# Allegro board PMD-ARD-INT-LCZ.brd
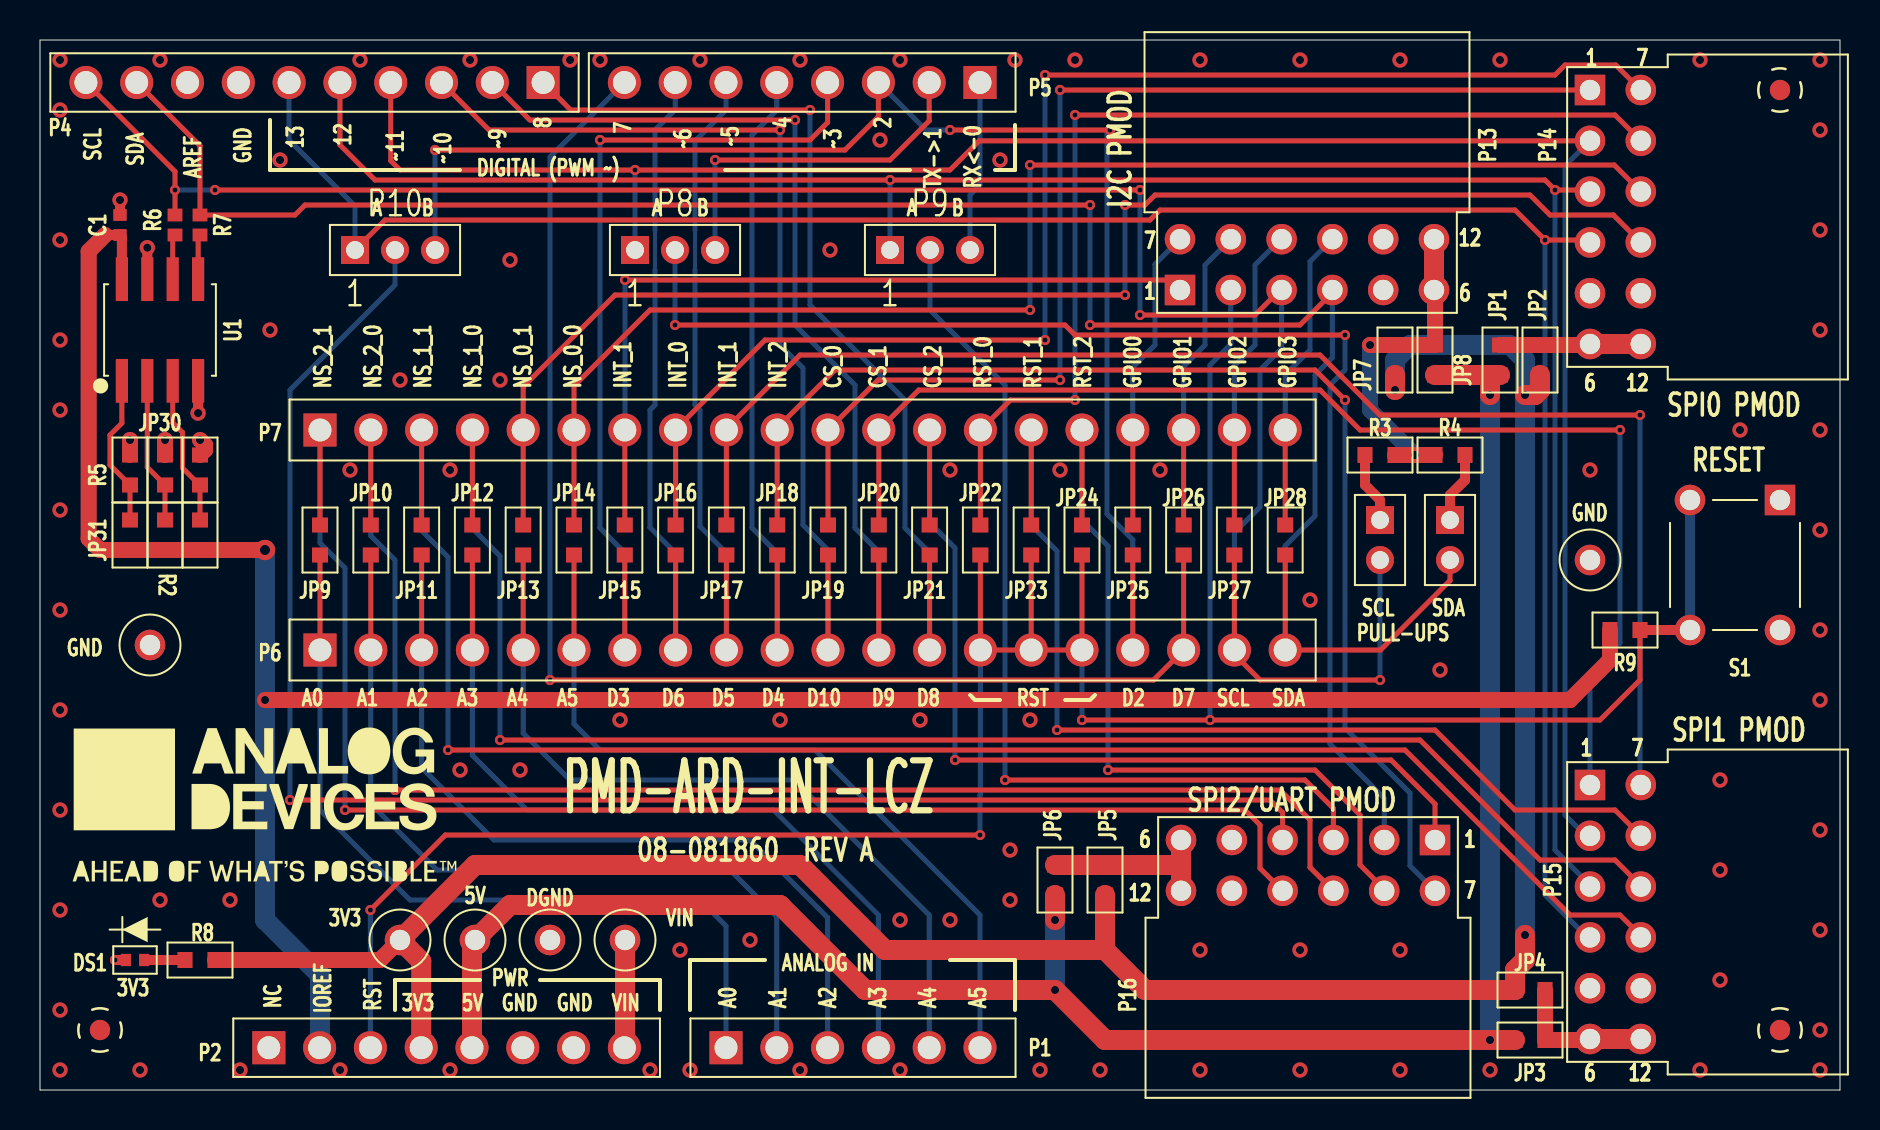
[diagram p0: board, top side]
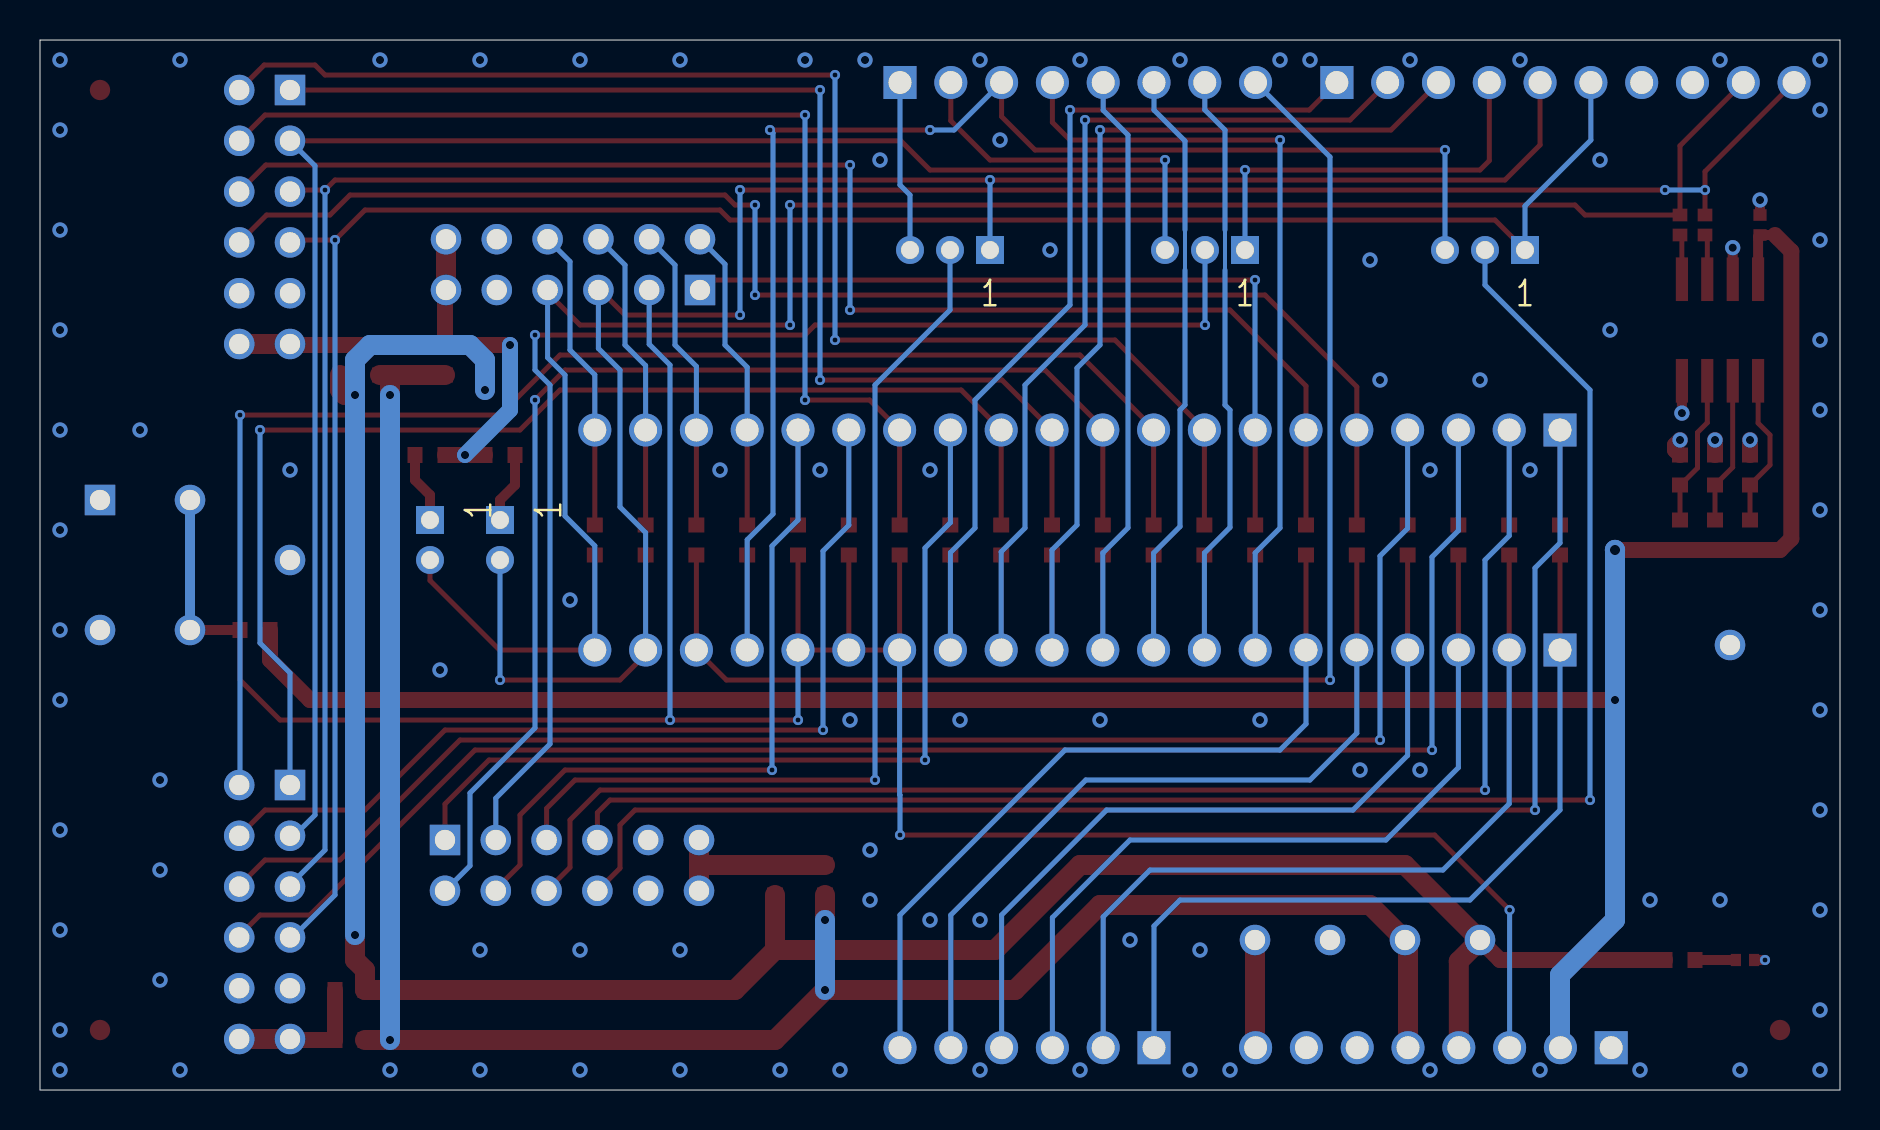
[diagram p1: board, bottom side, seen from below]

Outline 90 x 52.5 mm; copper layers: TOP, LAYER2, LAYER3, BOTTOM. Coordinates in mm from the lower left corner of the outline.
Outline path: 0,52.5 90,52.5 90,0 0,0 0,52.5

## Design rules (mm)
constraint set DEFAULT: min track width 0.15

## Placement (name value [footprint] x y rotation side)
C1  0.1uF  [C0402]  4 43.25 270 top
DGND  BLK  [CNKEY5001TP]  25.5 7.5 0 top
DGND1  BLK  [CNKEY5001TP]  5.5 22.25 0 top
DGND2  BLK  [CNKEY5001TP]  77.5 26.5 0 top
DS1  SML-P11MTT86R  [LED0402]  4.75 6.5 0 top
JP1  0  [R0603]  73 36.5 90 top
JP2  0  [R0603]  75 36.5 90 top
JP3  0  [R0603]  74.5 2.5 0 top
JP4  0  [R0603]  74.5 5 0 top
JP5  0  [R0603]  53.25 10.5 90 top
JP6  0  [R0603]  50.75 10.5 90 top
JP7  0  [R0603]  67.75 36.5 90 top
JP8  0  [R0603]  69.75 36.5 90 top
JP9  0  [R0603]  14 27.5 90 top
JP10  0  [R0603]  16.54 27.5 90 top
JP11  0  [R0603]  19.08 27.5 90 top
JP12  0  [R0603]  21.62 27.5 90 top
JP13  0  [R0603]  24.16 27.5 90 top
JP14  0  [R0603]  26.7 27.5 90 top
JP15  0  [R0603]  29.24 27.5 90 top
JP16  0  [R0603]  31.78 27.5 90 top
JP17  0  [R0603]  34.32 27.5 90 top
JP18  0  [R0603]  36.86 27.5 90 top
JP19  0  [R0603]  39.4 27.5 90 top
JP20  0  [R0603]  41.94 27.5 90 top
JP21  0  [R0603]  44.48 27.5 90 top
JP22  0  [R0603]  47.02 27.5 90 top
JP23  0  [R0603]  49.56 27.5 90 top
JP24  0  [R0603]  52.1 27.5 90 top
JP25  0  [R0603]  54.64 27.5 90 top
JP26  0  [R0603]  57.18 27.5 90 top
JP27  0  [R0603]  59.72 27.5 90 top
JP28  0  [R0603]  62.26 27.5 90 top
JP29  0  [R0603]  8 27.75 270 top
JP30  0  [R0603]  6.25 31 270 top
JP31  0  [R0603]  4.5 27.75 270 top
NOREF  -  []  -67.5 -75.55 0 top
NOREF#2  -  []  366.75 248.75 0 top
NOREF#3  -  []  0 53 270 top
NOREF#4  -  [unnamed#2]  3 3 180 top
NOREF#5  -  []  -43.25 -76.25 0 top
NOREF#6  -  []  11.25 14.25 0 top
NOREF#7  -  []  -43.25 -76.25 0 top
NOREF#8  -  []  0 0 90 top
NOREF#9  -  [unnamed#2]  87 3 180 top
NOREF#10  -  []  0 0 0 top
NOREF#11  -  []  90 0 90 top
NOREF#12  -  [unnamed#2]  87 50 90 top
NOREF#13  -  []  90 52.5 180 top
NOREF#14  -  []  231.75 23.75 0 top
NOREF#15  -  []  45.75 -10.25 0 top
NOREF#16  -  []  0 52.5 0 top
NOREF#17  -  []  -33.25 323.75 0 top
P1  SSQ-106-03-T-S  [CNSAMTECSSQ-106-XX-X-S]  34.3 2.12 0 top
P2  SSQ-108-03-T-S  [CNSAMTECSSQ-108-XX-X-S]  11.44 2.12 0 top
P4  SSQ-110-03-T-S  [CNSAMTECSSQ-110-XX-X-S]  25.16 50.38 180 top
P5  SSQ-108-03-T-S  [CNSAMTECSSQ-108-XX-X-S]  47 50.38 180 top
P6  TSW-120-17-T-S  [CNTHMHDR1X20L2000W100H733]  14 22 0 top
P7  TSW-120-17-T-S  [CNTHMHDR1X20L2000W100H733]  14 33 0 top
P8  62000311121  [CNTHMHDR1X3L236W79H244]  29.75 42 0 top
P9  62000311121  [CNTHMHDR1X3L236W79H244]  42.5 42 0 top
P10  62000311121  [CNTHMHDR1X3L236W79H244]  15.75 42 0 top
P11  62000211121  [CNTHMHDR1X2L157W79H250]  67 28.5 270 top
P12  62000211121  [CNTHMHDR1X2L157W79H250]  70.5 28.5 270 top
P13  PPPC062LJBN-RC  [CNHDRRA2X6H205]  57 40 0 top
P14  PPPC062LJBN-RC  [CNHDRRA2X6H205]  77.5 50 270 top
P15  Ø  [CNHDRRA2X6H205]  77.5 15.25 270 top
P16  PPPC062LJBN-RC  [CNHDRRA2X6H205]  69.75 12.5 180 top
R1  4.7K  [R0603]  8 31 270 top
R2  4.7K  [R0603]  6.25 27.75 270 top
R3  4.7K  [R0603]  67 31.75 0 top
R4  4.7K  [R0603]  70.5 31.75 180 top
R5  4.7K  [R0603]  4.5 31 270 top
R6  0  [R0402]  6.75 43.25 90 top
R7  0  [R0402]  8 43.25 90 top
R8  1K  [R0603]  8 6.5 0 top
R9  1K  [R0603]  79.25 23 180 top
S1  1825910-6  [SWTHSQ236H209]  87 29.5 180 top
U1  24AA32A-I/SN  [SO8]  6 38 0 top
UNK3V3  BLK  [CNKEY5001TP]  18 7.5 0 top
UNK5V  BLK  [CNKEY5001TP]  21.75 7.5 0 top
VIN  BLK  [CNKEY5001TP]  29.25 7.5 0 top

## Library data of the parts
C1 = CAP: User Part Number: UPN; Tolerance: 10; alternate symbols: (C0402); part number: CAP_SM-0.1UF,50V,10,E025746,C0402; tolerance: 10
DGND DGND1 DGND2 UNK3V3 UNK5V VIN = CNTP1P: Tolerance: N/A; User Part Number: UPN; alternate symbols: (CNKEY5001TP); part number: CNTP1P_TH-BLK,E022951,CNKEY5001TP; tolerance: N/A
DS1 = DIOLED: User Part Number: UPN; Tolerance: N/A; alternate symbols: (LED0402); part number: DIOLED_SM-SML-P11MTT86R,N/A,N/A,E014445,LED0402; tolerance: N/A
JP1-JP31 = RESJMPRSHRT: User Part Number: UPN; Tolerance: JUMPER; alternate symbols: (R0603); part number: RESJMPRSHRT_SM-0,E004447,1/10W,JUMPER,R0603; tolerance: JUMPER
P1 = CN6P: User Part Number: UPN; Tolerance: N/A; alternate symbols: (CNSAMTECSSQ-106-XX-X-S); part number: CN6P_TH-SSQ-106-03-T-S,E027150,CNSAMTECSSQ-106-XX-X-S; tolerance: N/A
P2 P5 = CN8P_A: User Part Number: UPN; Tolerance: N/A; alternate symbols: (CNSAMTECSSQ-108-XX-X-S); part number: CN8P_A_TH-SSQ-108-03-T-S,E027149,CNSAMTECSSQ-108-XX-X-S; tolerance: N/A
P4 = CN10P: User Part Number: UPN; Tolerance: N/A; alternate symbols: (CNSAMTECSSQ-110-XX-X-S); part number: CN10P_TH-SSQ-110-03-T-S,E027151,CNSAMTECSSQ-110-XX-X-S; tolerance: N/A
P6 P7 = CN20P: User Part Number: UPN; Tolerance: N/A; alternate symbols: (CNTHMHDR1X20L2000W100H733); part number: CN20P_TH-TSW-120-17-T-S,E055627,CNTHMHDR1X20L2000W100H733; tolerance: N/A
P8-P10 = CN3P: User Part Number: UPN; Tolerance: N/A; alternate symbols: (CNTHMHDR1X3L236W79H244); part number: CN3P_TH-62000311121,E033291,CNTHMHDR1X3L236W79H244; tolerance: N/A
P11 P12 = CN2P: User Part Number: UPN; Tolerance: N/A; alternate symbols: (CNTHMHDR1X2L157W79H250); part number: CN2P_TH-62000211121,E035205,CNTHMHDR1X2L157W79H250; tolerance: N/A
P13-P16 = CN12P_V3: User Part Number: UPN; Tolerance: N/A; alternate symbols: (CNHDRRA2X6H205); part number: CN12P_V3_TH-PPPC062LJBN-RC,E022332,CNHDRRA2X6H205; tolerance: N/A
R1-R5 = RES: User Part Number: UPN; Tolerance: 5; alternate symbols: (R0603); part number: RES_SM-4.7K,E031875,1/10W,5,R0603; tolerance: 5
R6 R7 = RES: User Part Number: UPN; Tolerance: JUMPER; alternate symbols: (R0402); part number: RES_SM-0,E003438,1/10W,JUMPER,R0402; tolerance: JUMPER
R8 R9 = RES: User Part Number: UPN; Tolerance: 1; alternate symbols: (R0603); part number: RES_SM-1K,E029591,1/10W,1,R0603; tolerance: 1
S1 = SWSPST4PIN_B: Tolerance: N/A; User Part Number: UPN; alternate symbols: (SWTHSQ236H209); part number: SWSPST4PIN_B_TH-1825910-6,E039562,SWTHSQ236H209; tolerance: N/A
U1 = IC24XX32A_V2: Tolerance: N/A; User Part Number: UPN; alternate symbols: (SO8); part number: IC24XX32A_V2_SM-24AA32A-I/SN,E034913,SO8; tolerance: N/A

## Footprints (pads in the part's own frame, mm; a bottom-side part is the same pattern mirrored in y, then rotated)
C0402
  rect 0.584x0.66 smd: 1(-0.5,0) 2(0.5,0)
CNHDRRA2X6H205
  rect 1.524x1.524 hole 1.016: 1(0,0)
  round 1.524 hole 1.016: 2(2.54,0) 3(5.08,0) 4(7.62,0) 5(10.16,0) 6(12.7,0) 7(0,2.54) 8(2.54,2.54) 9(5.08,2.54) 10(7.62,2.54) 11(10.16,2.54) 12(12.7,2.54)
CNKEY5001TP
  round 1.524 hole 1.016: 1(0,0)
CNSAMTECSSQ-106-XX-X-S
  rect 1.651x1.651 hole 1.143: 1(0,0)
  round 1.651 hole 1.143: 2(2.54,0) 3(5.08,0) 4(7.62,0) 5(10.16,0) 6(12.7,0)
CNSAMTECSSQ-108-XX-X-S
  rect 1.651x1.651 hole 1.143: 1(0,0)
  round 1.651 hole 1.143: 2(2.54,0) 3(5.08,0) 4(7.62,0) 5(10.16,0) 6(12.7,0) 7(15.24,0) 8(17.78,0)
CNSAMTECSSQ-110-XX-X-S
  rect 1.651x1.651 hole 1.143: 1(0,0)
  round 1.651 hole 1.143: 2(2.54,0) 3(5.08,0) 4(7.62,0) 5(10.16,0) 6(12.7,0) 7(15.24,0) 8(17.78,0) 9(20.32,0) 10(22.86,0)
CNTHMHDR1X2L157W79H250
  rect 1.397x1.397 hole 0.889: 1(0,0)
  round 1.397 hole 0.889: 2(2,0)
CNTHMHDR1X3L236W79H244
  rect 1.397x1.397 hole 0.889: 1(0,0)
  round 1.397 hole 0.889: 2(2,0) 3(4,0)
CNTHMHDR1X20L2000W100H733
  rect 1.651x1.651 hole 1.143: 1(0,0)
  round 1.651 hole 1.143: 2(2.54,0) 3(5.08,0) 4(7.62,0) 5(10.16,0) 6(12.7,0) 7(15.24,0) 8(17.78,0) 9(20.32,0) 10(22.86,0) 11(25.4,0) 12(27.94,0) 13(30.48,0) 14(33.02,0) 15(35.56,0) 16(38.1,0) 17(40.64,0) 18(43.18,0) 19(45.72,0) 20(48.26,0)
LED0402
  rect 0.508x0.61 smd: A(0.454,0) C(-0.454,0)
R0402
  rect 0.635x0.737 smd: 1(-0.5,0) 2(0.5,0)
R0603
  rect 0.75x0.8 smd: 1(-0.75,0) 2(0.75,0)
SO8
  rect 0.61x2.184 smd: 1(-1.905,-2.54) 2(-0.635,-2.54) 3(0.635,-2.54) 4(1.905,-2.54) 5(1.905,2.54) 6(0.635,2.54) 7(-0.635,2.54) 8(-1.905,2.54)
SWTHSQ236H209
  rect 1.524x1.524 hole 1.016: 1(0,0)
  round 1.524 hole 1.016: 2(0,6.5) 3(4.5,0) 4(4.5,6.5)
unnamed#2
  round 1.016 smd: (0,0)

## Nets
3V3_ARD: JP2.1 JP4.1 JP5.1 JP7.1 P2.4 R8.2(N2) UNK3V3.1
5V_ARD: JP1.1 JP3.1 JP6.1 JP8.1 P2.5 UNK5V.1
DGND: C1.1 DGND.1(N1) DGND1.1(N1) DGND2.1(N1) DS1.C JP30.1 P2.6 P2.7 P4.7 P13.5 P13.11 P14.5 P14.11 P15.5 P15.11 P16.5 P16.11 R1.1 R5.1 S1.1 S1.2 U1.4 U1.7(WP)
VIN: P2.8(N8) VIN.1(N1)
A0: JP9.1 P1.1 P6.1
A1: JP10.1 P1.2 P6.2
A2: JP11.1 P1.3 P6.3
A3: JP12.1 P1.4 P6.4
A4: JP13.1 P1.5 P6.5
A5: JP14.1 P1.6(N6) P6.6
CS_0: JP19.2(S2) P7.11 P14.1
CS_1: JP20.2(S2) P7.12 P15.1
CS_2: JP21.2(S2) P7.13 P16.1
D2: JP25.1 P5.3 P6.17 P10.3(N3)
D3: JP15.1 P5.4 P6.7
D4: JP18.1 P5.5 P6.10
D5: JP17.1 P5.6 P6.9(N9)
D6: JP16.1 P5.7 P6.8
D7: JP26.1 P5.8(N8) P6.18
D8: JP21.1 P4.1 P6.13
D9: JP20.1 P4.2 P6.12
D10: JP19.1 P4.3 P6.11
GPIO0: JP25.2(S2) P7.17 P13.7
GPIO1: JP26.2(S2) P7.18 P13.8
GPIO2: JP27.2(S2) P7.19 P13.9
GPIO3: JP28.2(S2) P7.20 P13.10
INT_0: JP16.2(S2) P7.8 P14.7
INT_1: JP17.2(S2) P7.9(N9) P15.7
INT_2: JP18.2(S2) P7.10 P16.7
INT_I: JP15.2(S2) P7.7 P13.1
IOREF_ARD: C1.2(N2) JP29.2(S2) JP31.2(S2) P2.2 R2.2(N2) R9.2(N2) U1.8
MISO_ARD: P4.5 P9.1 P14.3 P15.3
MOSI_ARD: P4.4 P8.1 P14.2 P15.2
NS_0_0: JP14.2(S2) P7.6 P14.9
NS_0_1: JP13.2(S2) P7.5 P14.10
NS_1_0: JP12.2(S2) P7.4 P15.9
NS_1_1: JP11.2(S2) P7.3 P15.10
NS_2_0: JP10.2(S2) P7.2 P16.9
NS_2_1: JP9.2(S2) P7.1 P16.10
RST_0: JP22.2(S2) P7.14 P14.8
RST_1: JP23.2(S2) P7.15 P15.8
RST_2: JP24.2(S2) P7.16 P16.8
RST_ARD: JP22.1 JP23.1 JP24.1 P2.3 P6.14 P6.15 P6.16 P13.2 R9.1 S1.3 S1.4(N4)
RX_ARD: P5.1 P9.3(N3)
SCK_ARD: P4.6 P10.1 P14.4 P15.4
SCL_ARD: JP27.1 P4.10 P6.19 P11.2(N2) P13.3 R6.2(N2)
SDA_ARD: JP28.1 P4.9(N9) P6.20 P12.2(N2) P13.4 R7.2(N2)
TX_ARD: P5.2 P8.3(N3)
UNNAMED_2_CN12PV3_I122_P2: P8.2 P16.2
UNNAMED_2_CN12PV3_I122_P3: P9.2 P16.3
UNNAMED_2_CN12PV3_I122_P4: P10.2 P16.4
UNNAMED_2_RES_I93_N1: P12.1 R4.1
UNNAMED_2_RES_I107_N1: P11.1 R3.1
UNNAMED_4_DIOLED_I89_P: DS1.A(P) R8.1
UNNAMED_4_IC24XX32AV2_I37_A0: JP31.1 R5.2(N2) U1.1
UNNAMED_4_IC24XX32AV2_I37_A1: JP30.2(S2) R2.1 U1.2
UNNAMED_4_IC24XX32AV2_I37_A2: JP29.1 R1.2(N2) U1.3
UNNAMED_4_IC24XX32AV2_I37_SCL: R6.1 U1.6
UNNAMED_4_IC24XX32AV2_I37_SDA: R7.1 U1.5
VPMOD_I2C: JP7.2(S2) JP8.2(S2) P13.6 P13.12(VCC2) R3.2(N2) R4.2(N2)
VPMOD_SPI0: JP1.2(S2) JP2.2(S2) P14.6 P14.12(VCC2)
VPMOD_SPI1: JP3.2(S2) JP4.2(S2) P15.6 P15.12(VCC2)
VPMOD_SPI2: JP5.2(S2) JP6.2(S2) P16.6 P16.12(VCC2)

Pads without a net: P2 1; P4 8

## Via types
v1: diameter 0.762, hole 0.406, TOP to BOTTOM, 107 vias
v2: diameter 0.508, hole 0.254, TOP to BOTTOM, 50 vias
v3: diameter 1.016, hole 0.508, TOP to BOTTOM, 1 via

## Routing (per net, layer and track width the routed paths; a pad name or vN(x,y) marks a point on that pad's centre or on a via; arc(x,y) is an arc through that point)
3V3_ARD: length 120.8
  TOP w0.8: R8.2 17,6.5 UNK3V3.1
  TOP w1: v1(74.25,34.75) 74.75,34.75 75,35 JP2.1 ; 53.25,7 42.25,7 38,11.25 21.75,11.25 UNK3V3.1 19.06,6.44 P2.4 ; 53.25,7 55.25,5 JP4.1 73.75,6 74.25,6.5 v1(74.25,7.75) ; 53.25,7 JP5.1 ; JP7.1 v1(67.75,35)
  BOTTOM w1: v1(67.75,35) 67.75,36.5 68.5,37.25 73.5,37.25 74.25,36.5 v1(74.25,34.75) v1(74.25,7.75)
5V_ARD: length 102.2
  TOP w1: JP6.1 v1(50.75,8.5) ; 72.55,35.75 JP1.1 ; 72.55,35.75 72.5,35.7 v1(72.5,34.75) ; 72.55,35.75 JP8.1 ; JP3.1 v1(72.5,2.5) 53.25,2.5 v1(50.75,5) 41.25,5 37,9.25 23.5,9.25 UNK5V.1 21.6,7.35 P2.5
  BOTTOM w1: v1(72.5,34.75) v1(72.5,2.5) ; v1(50.75,8.5) v1(50.75,5)
DGND: length 144.6
  TOP w0.5: C1.1 v1(4,44.5) ; U1.4 v1(7.91,33.84) ; U1.7 v1(5.37,42.12) ; DS1.C v2(3.75,6.5)
  TOP w0.8: v1(8,32.5) 8.25,32.25 8.25,32 R1.1 ; JP30.1 v1(6.25,32.5) ; R5.1 v1(4.5,32.5)
  LAYER2 w0.35: P2.6 24.14,3.24 ; P2.6 23.01,2.12 ; P2.6 24.14,0.99 ; P2.6 25.27,2.12 ; 85.94,23 S1.2 ; S1.2 87,24.06 ; S1.2 87,21.94 ; S1.2 88.06,23 ; P15.5 77.5,6.15 ; P15.5 77.5,4.03 ; P15.5 76.44,5.09 ; P15.5 78.56,5.09 ; DGND.1 26.56,7.5 ; DGND.1 25.5,6.44 ; DGND.1 25.5,8.56 ; DGND.1 24.44,7.5 ; P16.5 60.65,12.5 ; P16.5 59.59,11.44 ; P16.5 59.59,13.56 ; P16.5 58.53,12.5 ; P14.11 80.04,40.9 ; P14.11 80.04,38.78 ; P14.11 81.1,39.84 ; P14.11 78.98,39.84 ; 4.44,22.25 DGND1.1 ; DGND1.1 5.5,23.31 ; DGND1.1 5.5,21.19 ; DGND1.1 6.56,22.25 ; P15.11 80.04,6.15 ; P15.11 81.1,5.09 ; P15.11 78.98,5.09 ; P15.11 80.04,4.03 ; 87,28.44 S1.1 ; S1.1 87,30.56 ; S1.1 88.06,29.5 ; S1.1 85.94,29.5 ; P16.11 60.65,9.96 ; P16.11 59.59,8.9 ; P16.11 59.59,11.02 ; P16.11 58.53,9.96 ; P2.7 27.81,2.12 ; P2.7 26.68,3.24 ; P2.7 26.68,0.99 ; P2.7 25.55,2.12 ; DGND2.1 78.56,26.5 ; DGND2.1 77.5,27.56 ; DGND2.1 76.44,26.5 ; DGND2.1 77.5,25.44 ; P4.7 11.04,50.38 ; P4.7 8.79,50.38 ; P4.7 9.92,49.25 ; P4.7 9.92,51.5 ; 67.16,38.94 P13.5 ; P13.5 67.16,41.06 ; P13.5 66.1,40 ; P13.5 68.22,40 ; P14.5 77.5,40.9 ; P14.5 76.44,39.84 ; P14.5 77.5,38.78 ; P14.5 78.56,39.84 ; P13.11 68.22,42.54 ; P13.11 67.16,43.6 ; P13.11 66.1,42.54 ; P13.11 67.16,41.48
  LAYER3 w0.35: DGND.1 26.56,7.5 ; DGND.1 25.5,6.44 ; DGND.1 24.44,7.5 ; DGND.1 25.5,8.56 ; 87,21.94 S1.2 ; S1.2 88.06,23 ; S1.2 87,24.06 ; S1.2 85.94,23 ; P2.7 26.68,3.24 ; P2.7 27.81,2.12 ; P2.7 26.68,0.99 ; P2.7 25.55,2.12 ; 78.98,39.84 P14.11 ; P14.11 80.04,38.78 ; P14.11 81.1,39.84 ; P14.11 80.04,40.9 ; P15.11 80.04,6.15 ; P15.11 78.98,5.09 ; P15.11 80.04,4.03 ; P15.11 81.1,5.09 ; 59.59,11.44 P16.5 ; P16.5 58.53,12.5 ; P16.5 59.59,13.56 ; P16.5 60.65,12.5 ; 76.44,39.84 P14.5 ; P14.5 77.5,40.9 ; P14.5 78.56,39.84 ; P14.5 77.5,38.78 ; 77.5,25.44 DGND2.1 ; DGND2.1 76.44,26.5 ; DGND2.1 77.5,27.56 ; DGND2.1 78.56,26.5 ; P2.6 25.27,2.12 ; P2.6 23.01,2.12 ; P2.6 24.14,3.24 ; P2.6 24.14,0.99 ; S1.1 88.06,29.5 ; S1.1 87,28.44 ; S1.1 85.94,29.5 ; S1.1 87,30.56 ; P16.11 59.59,11.02 ; P16.11 59.59,8.9 ; P16.11 58.53,9.96 ; P16.11 60.65,9.96 ; P15.5 77.5,6.15 ; P15.5 76.44,5.09 ; P15.5 77.5,4.03 ; P15.5 78.56,5.09 ; 67.16,41.48 P13.11 ; P13.11 68.22,42.54 ; P13.11 66.1,42.54 ; P13.11 67.16,43.6 ; 8.79,50.38 P4.7 ; P4.7 11.04,50.38 ; P4.7 9.92,51.5 ; P4.7 9.92,49.25 ; 66.1,40 P13.5 ; P13.5 67.16,38.94 ; P13.5 67.16,41.06 ; P13.5 68.22,40 ; DGND1.1 6.56,22.25 ; DGND1.1 5.5,21.19 ; DGND1.1 5.5,23.31 ; DGND1.1 4.44,22.25
  vias: v1(1,51.5) v1(1,49) v1(1,42.5) v1(1,37.5) v1(1,34) v1(1,29) v1(1,24) v1(1,19) v1(1,14) v1(1,9) v1(1,4) v1(1,1) v1(5,1) v1(6,51.5) v1(6,9.5) v1(9.5,9.5) v1(10,1) v1(11.5,38) v1(12,46.5) v1(15,1) v1(15.5,31) v1(16,51.5) v1(18,35.5) v1(20.5,31) v1(20.5,1) v1(21,16) v1(21.5,51.5) v1(23,35.5) v1(23.5,41.5) v1(24,16) v1(26.5,51.5) v1(28,51.5) v1(29,18.5) v1(30.5,1) v1(32,7) v1(32.5,1) v1(33,51.5) v1(35.5,7.5) v1(37,18.5) v1(38,51.5) v1(38,1) v1(39.5,42) v1(42,47.5) v1(43,51.5) v1(43,8.5) v1(43,1) v1(44,18.5) v1(45.5,31) v1(45.5,8.5) v1(48,46.5) v1(48.5,12) v1(48.5,9.5) v1(48.75,51.5) v1(49.5,18.5) v1(50,1) v1(51,31) v1(51.75,51.5) v1(53,1) v1(56,31) v1(58,51.5) v1(58,7) v1(58,1) v1(63,51.5) v1(63,7) v1(63,1) v1(63.5,24.5) v1(68,51.5) v1(68,7) v1(68,1) v1(70,21) v1(72.5,1) v1(73,51.5) v1(77.5,31) v1(83,51.5) v1(83,1) v1(84,15.5) v1(84,11) v1(84,5.5) v1(85,33) v1(89,51.5) v1(89,48) v1(89,43) v1(89,38) v1(89,33) v1(89,28) v1(89,23) v1(89,19.5) v1(89,13) v1(89,8) v1(89,3) v1(89,1)
VIN: length 5.4
  TOP w1: P2.8 29.25,2.15 VIN.1
A0: length 41.5
  TOP w0.25: P6.1 JP9.1
  BOTTOM w0.25: P1.1 34.3,8.2 33,9.5 18.5,9.5 14,14 P6.1
A1: length 41.6
  TOP w0.25: P6.2 JP10.1
  BOTTOM w0.25: P6.2 16.54,14.31 19.85,11 34.5,11 36.84,8.66 P1.2
A2: length 40.5
  TOP w0.25: P6.3 JP11.1
  BOTTOM w0.25: P1.3 39.38,8.62 35.5,12.5 22.7,12.5 19.08,16.12 P6.3
A3: length 40.3
  TOP w0.25: P6.4 JP12.1
  BOTTOM w0.25: P6.4 21.62,16.73 24.35,14 36.67,14 41.92,8.75 P1.4
A4: length 39.6
  TOP w0.25: P6.5 JP13.1
  BOTTOM w0.25: P1.5 44.46,8.75 37.71,15.5 26.5,15.5 24.16,17.84 P6.5
A5: length 39.3
  TOP w0.25: P6.6 JP14.1
  BOTTOM w0.25: P1.6 47,8.75 38.75,17 28,17 26.7,18.3 P6.6
CS_0: length 58.4
  TOP w0.25: v2(51,35.5) 41.9,35.5 P7.11 JP19.2 ; v2(51,50) P14.1
  BOTTOM w0.25: v2(51,35.5) v2(51,50)
CS_1: length 61.8
  TOP w0.25: v2(79,33) 66,33 64,35 43.94,35 P7.12 JP20.2
  BOTTOM w0.25: P15.1 77.5,20.85 79,22.35 v2(79,33)
CS_2: length 48.5
  TOP w0.25: P7.13 JP21.2 ; v2(45.75,16.5) 67.55,16.5 69.75,14.3 P16.1
  BOTTOM w0.25: P7.13 44.48,28.37 45.75,27.1 v2(45.75,16.5)
D2: length 73.5
  TOP w0.25: v2(19.75,47) 40.25,47 41.92,48.67 P5.3 ; v2(53.5,48) v2(45.5,48) ; JP25.1 P6.17
  BOTTOM w0.25: P5.3 44.3,48 v2(45.5,48) ; P10.3 v2(19.75,47) ; v2(53.5,48) 53.35,47.85 53.35,28.8 54.64,27.51 P6.17
D3: length 44.5
  TOP w0.25: P5.4 39.38,48.38 38.5,47.5 v2(28,47.5) ; P6.7 JP15.1
  BOTTOM w0.25: v2(28,47.5) 28,28.1 29.24,26.86 P6.7
D4: length 34.2
  TOP w0.25: P6.10 JP18.1
  BOTTOM w0.25: P6.10 36.86,26.85 35.6,28.11 35.6,47.75 36.84,48.99 P5.5
D5: length 34.4
  TOP w0.25: P6.9 JP17.1
  BOTTOM w0.2: 32.75,41 32.75,43
  BOTTOM w0.25: P6.9 34.32,26.85 33,28.17 33,34 32.75,34.25 32.75,41 ; 32.75,43 32.75,47.45 34.3,49 P5.6
D6: length 34.2
  TOP w0.25: P6.8 JP16.1
  BOTTOM w0.2: 30.75,41 30.75,43
  BOTTOM w0.25: P5.7 31.76,49.01 30.75,48 30.75,43 ; P6.8 31.78,26.85 30.5,28.13 30.5,34 30.75,34.25 30.75,41
D7: length 68.5
  TOP w0.25: JP26.1 P6.18 55.68,20.5 v2(25.5,20.5)
  BOTTOM w0.25: v2(25.5,20.5) 25.5,46.66 P5.8
D8: length 48.1
  TOP w0.25: P6.13 JP21.1 ; v2(38.5,49) 26.53,49 P4.1
  BOTTOM w0.25: P6.13 44.48,26.87 43.25,28.1 43.25,34.5 38.5,39.25 v2(38.5,49)
D9: length 48.9
  TOP w0.25: P4.2 24.49,48.5 v2(37.75,48.5) ; P6.12 JP20.1
  BOTTOM w0.25: P6.12 41.94,26.91 40.75,28.1 40.75,35.25 37.75,38.25 v2(37.75,48.5)
D10: length 49.7
  TOP w0.25: P6.11 JP19.1 ; P4.3 22.45,48 v2(37,48)
  BOTTOM w0.25: v2(37,48) 37,37.25 38.15,36.1 38.15,28.25 39.4,27 P6.11
GPIO0: length 15.3
  TOP w0.25: JP25.2 P7.17
  BOTTOM w0.25: P7.17 54.64,36.14 55.75,37.25 55.75,41.29 P13.7
GPIO1: length 15.3
  TOP w0.25: JP26.2 P7.18
  BOTTOM w0.25: P13.8 58.25,41.25 58.25,37.25 57.18,36.18 P7.18
GPIO2: length 15.3
  TOP w0.25: JP27.2 P7.19
  BOTTOM w0.25: P13.9 62.04,42.54 60.75,41.25 60.75,37.25 59.72,36.22 P7.19
GPIO3: length 15.3
  TOP w0.25: JP28.2 P7.20
  BOTTOM w0.25: P7.20 62.26,35.76 63.5,37 63.5,41.42 P13.10
INT_0: length 68.9
  TOP w0.25: v2(50.25,50.75) 75.75,50.75 76.25,51.25 78.79,51.25 P14.7 ; JP16.2 P7.8 31.78,33.03 36.25,37.5 v2(50.25,37.5)
  BOTTOM w0.25: v2(50.25,37.5) v2(50.25,50.75)
INT_1: length 71.8
  TOP w0.25: JP17.2 P7.9 34.32,33.07 38,36.75 64,36.75 67,33.75 v2(80,33.75)
  BOTTOM w0.25: v2(80,33.75) 80,15.29 P15.7
INT_2: length 61.5
  TOP w0.25: P16.7 69.75,10 ; v2(65.25,34.5) 63.75,36 39.75,36 36.86,33.11 P7.10 JP18.2
  BOTTOM w0.25: P16.7 68.5,11.21 68.5,14.85 65.25,18.1 v2(65.25,34.5)
INT_I: length 40.2
  TOP w0.25: JP15.2 P7.7 ; v2(29.25,40.5) 56.5,40.5 P13.1
  BOTTOM w0.25: v2(29.25,40.5) 29.25,33.01 P7.7
IOREF_ARD: length 123.2
  TOP w0.5: U1.8 4.09,42.66 C1.2 3.25,42.75
  TOP w0.8: v3(11.25,27) JP29.2 R2.2 JP31.2 3,27 2.43,27.57 2.43,41.93 3.25,42.75 ; R9.2 78.5,21.5 76.5,19.5 v1(11.25,19.5)
  BOTTOM w1: v3(11.25,27) v1(11.25,19.5) 11.25,8.5 14,5.75 14,2.13 P2.2
MISO_ARD: length 105.6
  TOP w0.25: P4.5 15,47.25 16.75,45.5 v2(42.5,45.5) 75.25,45.5 v2(75.75,45) 77.42,45 P14.3
  BOTTOM w0.25: v2(42.5,45.5) P9.1 ; v2(75.75,45) 75.75,12 77.5,10.25 P15.3
MOSI_ARD: length 104.6
  TOP w0.25: P4.4 17.54,46.46 18,46 v2(29.75,46) 45.5,46 46.96,47.46 P14.2
  BOTTOM w0.25: v2(29.75,46) P8.1 ; P14.2 76.25,46.21 76.25,13.75 77.29,12.71 P15.2
NS_0_0: length 69.7
  TOP w0.25: P14.9 78.71,46.25 v2(49.5,46.25) ; JP14.2 P7.6 26.7,35.2 30.5,39 v2(49.5,39)
  BOTTOM w0.25: v2(49.5,39) v2(49.5,46.25)
NS_0_1: length 70.4
  TOP w0.25: P14.10 78.67,43.75 75.5,43.75 74.5,44.75 55.75,44.75 55.25,44.25 v2(54.25,44.25) ; v2(54.25,39.75) 28.75,39.75 24.16,35.16 P7.5 JP13.2
  BOTTOM w0.25: v2(54.25,39.75) v2(54.25,44.25)
NS_1_0: length 80.9
  TOP w0.25: v2(23,17.5) 69,17.5 75,11.5 78.75,11.5 80.04,10.21 P15.9 ; JP12.2 P7.4
  BOTTOM w0.25: v2(23,17.5) 23,26.7 21.62,28.08 P7.4
NS_1_1: length 84.9
  TOP w0.25: v2(20.4,17) 68.25,17 76.5,8.75 79,8.75 80.04,7.71 P15.10 ; JP11.2 P7.3
  BOTTOM w0.25: v2(20.4,17) 20.4,26.65 19.08,27.97 P7.3
NS_2_0: length 73.6
  TOP w0.25: JP10.2 P7.2 ; v2(17.75,15) 62,15 63.5,13.5 63.5,11.13 P16.9
  BOTTOM w0.25: v2(17.75,15) 17.75,26.5 16.54,27.71 P7.2
NS_2_1: length 74.1
  TOP w0.25: P16.10 61,11.09 61,13.25 60.25,14 v2(15.25,14) ; JP9.2 P7.1
  BOTTOM w0.25: P7.1 14,27.35 15.25,26.1 v2(15.25,14)
RST_0: length 53.2
  TOP w0.25: v2(51.75,48.75) 78.75,48.75 P14.8 ; v2(51.75,34.5) 48.52,34.5 P7.14 JP22.2
  BOTTOM w0.25: v2(51.75,48.75) v2(51.75,34.5)
RST_1: length 51.7
  TOP w0.25: P15.8 78.75,14 73.75,14 69.75,18 v2(50.85,18) ; JP23.2 P7.15
  BOTTOM w0.25: v2(50.85,18) 50.85,26.95 49.56,28.24 P7.15
RST_2: length 40.1
  TOP w0.25: JP24.2 P7.16 ; v2(53.4,16) 63.75,16 66,13.75 66,11.25 67.21,10.04 P16.8
  BOTTOM w0.25: v2(53.4,16) 53.4,27.2 52.1,28.5 P7.16
RST_ARD: length 133.2
  TOP w0.25: v2(52.1,18.5) v2(58.5,18.5) 78,18.5 80,20.5 R9.1 ; P6.15 P6.14 JP22.1 ; P6.15 JP23.1 ; P6.15 P6.16 JP24.1 ; v2(47,12.75) 20.27,12.75 v2(16.52,9)
  TOP w0.5: R9.1 S1.4
  BOTTOM w0.25: P13.2 59.54,37.29 58.5,36.25 v2(58.5,18.5) ; v2(16.52,9) P2.3 ; P6.14 47.02,14.77 47,14.75 v2(47,12.75) ; v2(52.1,18.5) P6.16
  BOTTOM w0.5: S1.3 S1.4
RX_ARD: length 8.6
  BOTTOM w0.25: P5.1 47,45.25 46.5,44.75 P9.3
SCK_ARD: length 108.9
  TOP w0.25: P10.1 17.25,43.5 55.5,43.5 56,44 73.75,44 v2(75.25,42.5) 77.38,42.5 P14.4
  BOTTOM w0.25: P15.4 77.37,7.63 75.25,9.75 v2(75.25,42.5) ; P4.6 12.46,47.49 15.75,44.2 P10.1
SCL_ARD: length 108.3
  TOP w0.25: v2(55,45) v2(8.75,45) ; R6.2 v2(6.75,45) 6.75,45.92 P4.10 ; P13.3 62,40 60.75,38.75 v2(55,38.75) ; v2(67,20.5) 61,20.5 59.72,21.78 P6.19 JP27.1
  BOTTOM w0.25: P6.19 59.72,27.87 61,29.15 61,36 62.08,37.08 P13.3 ; v2(67,20.5) P11.2 ; v2(6.75,45) v2(8.75,45) ; v2(55,38.75) v2(55,45)
SDA_ARD: length 106
  TOP w0.25: P12.2 70.5,25.48 67.02,22 P6.20 JP28.1 ; P4.9 8,47.21 R7.2 12.75,43.75 13.25,44.25 v2(52.5,44.25) ; P13.4 64.62,39.87 63,38.25 v2(52.5,38.25)
  BOTTOM w0.25: P6.20 62.26,27.21 63.75,28.7 63.75,35.75 64.62,36.62 P13.4 ; v2(52.5,38.25) v2(52.5,44.25)
TX_ARD: length 17.9
  TOP w0.25: v2(33.75,46.5) 42.5,46.5 44.46,48.46 P5.2
  BOTTOM w0.25: v2(33.75,46.5) P8.3
UNNAMED_2_CN12PV3_I122_P2: length 64.1
  TOP w0.25: v2(65.25,37.75) 51.75,37.75 51.25,38.25 v2(31.75,38.25)
  BOTTOM w0.25: P8.2 v2(31.75,38.25) ; P16.2 67.21,14.59 64.5,17.3 64.5,35.25 65.25,36 v2(65.25,37.75)
UNNAMED_2_CN12PV3_I122_P3: length 46.6
  TOP w0.25: v2(48.25,15.5) 63.25,15.5 64.67,14.08 P16.3
  BOTTOM w0.25: P9.2 44.5,39 48.25,35.25 v2(48.25,15.5)
UNNAMED_2_CN12PV3_I122_P4: length 80.9
  TOP w0.25: v2(12.5,14.5) 61.5,14.5 62.13,13.87 P16.4
  BOTTOM w0.25: v2(12.5,14.5) 12.5,35 17.75,40.25 P10.2
UNNAMED_2_RES_I93_N1: length 3.6
  TOP w0.5: R4.1 71.25,30.5 70.5,29.75 P12.1
UNNAMED_2_RES_I107_N1: length 3.6
  TOP w0.5: R3.1 66.25,30.25 67,29.5 P11.1
UNNAMED_4_DIOLED_I89_P: length 2
  TOP w0.5: R8.1 DS1.A
UNNAMED_4_IC24XX32AV2_I37_A0: length 7.6
  TOP w0.25: JP31.1 R5.2 3.5,31.25 3.5,32.75 4.09,33.34 U1.1
UNNAMED_4_IC24XX32AV2_I37_A1: length 7.3
  TOP w0.25: U1.2 5.37,31.14 JP30.2 R2.1
UNNAMED_4_IC24XX32AV2_I37_A2: length 7.5
  TOP w0.25: JP29.1 R1.2 7.97,30.25 7.12,31.1 7.12,32.88 6.63,33.36 U1.3
UNNAMED_4_IC24XX32AV2_I37_SCL: length 2.3
  TOP w0.25: U1.6 6.63,42.63 R6.1
UNNAMED_4_IC24XX32AV2_I37_SDA: length 2.2
  TOP w0.25: R7.1 7.91,42.66 U1.5
VPMOD_I2C: length 17
  TOP w0.8: 69.75,39.95 JP8.2 JP7.2 v1(66.5,37.25) ; R3.2 v1(68.75,31.75) R4.2
  TOP w1: 69.75,39.95 P13.6 P13.12
  BOTTOM w0.8: v1(66.5,37.25) 66.5,34 v1(68.75,31.75)
VPMOD_SPI0: length 7.1
  TOP w0.8: JP1.2 JP2.2 77.45,37.25 P14.6
  TOP w1: P14.12 P14.6
VPMOD_SPI1: length 7.3
  TOP w0.8: 77.45,2.5 JP3.2 JP4.2
  TOP w1: P15.12 P15.6 77.45,2.5
VPMOD_SPI2: length 8.8
  TOP w1: 57.05,11.25 P16.12 ; 57.05,11.25 JP5.2 JP6.2 ; 57.05,11.25 P16.6

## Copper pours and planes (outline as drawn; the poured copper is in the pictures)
DGND on LAYER2, LAYER3: 0.5,52 0.5,0.5 89.5,0.5 89.5,52

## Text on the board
User.Comments: COMPONENT KEEPOUT AREA | COMPONENTS GREATER THAN 1.5MM | ASSEMBLY NOTES: | 1. INSERT 2mm SHUNTS IN THE FOLLOWING LOCATIONS ... | 2. DO NOT TRIM LEADS OF P1, P2, P4 & P5. | INSERT PINS IN A FOAM BLOCK TO ENSURE THEY DONT BEND | DURING SHIPPING. | SEE NOTE-2 | LINK | P8 | P9 | P10 | P11 | P12 | INSERTED | A | POSITION
Ref Des/Silkscreen Top: GND | 3V3 | A0 | A1 | A | A2 | B | A3 | 5V | DIGITAL (PWM ~) | PWR | A4 | A5 | D3 | VIN | D6 | D5 | D4 | ANALOG IN | D10 | D9 | D8 | RST | D2 | D7 | SCL | SDA | PULL-UPS | AREF | NC | 13 | NS_2_1 | IOREF | 12 | NS_2_0 | ~11 | NS_1_1 | ~10 | NS_1_0 | ~9 | NS_0_1 | 8 | NS_0_0 | 7 | INT_1 | INT_0 | ~6 | ~5 | INT_2 | 4 | ~3 | CS_0 | CS_1 | 2 | TX->1 | CS_2 | RX<-0 | RST_0 | RST_1 | RST_2 | GPIO0 | GPIO1 | GPIO2 | GPIO3 | 08-081860  REV A | SPI2/UART PMOD | SPI0 PMOD | SPI1 PMOD | RESET | I2C PMOD | PMD-ARD-INT-LCZ
LAYER2: L2 Internal GND | 08-      -07
LAYER3: L3 POWER/GROUND | 08-      -08
User.28: 1 | FABRICATION | 09-012345-01 | A
User.29: FIGURE | FINISHED_SIZE | 0.254 | 0.4064 | 0.508 | 0.889 | 1.016 | 1.143 | DRILL CHART: TOP to BOTTOM | ALL UNITS ARE IN MILLIMETERS | PLATED | QTY | 50 | 108 | 1 | 13 | 58 | 72
